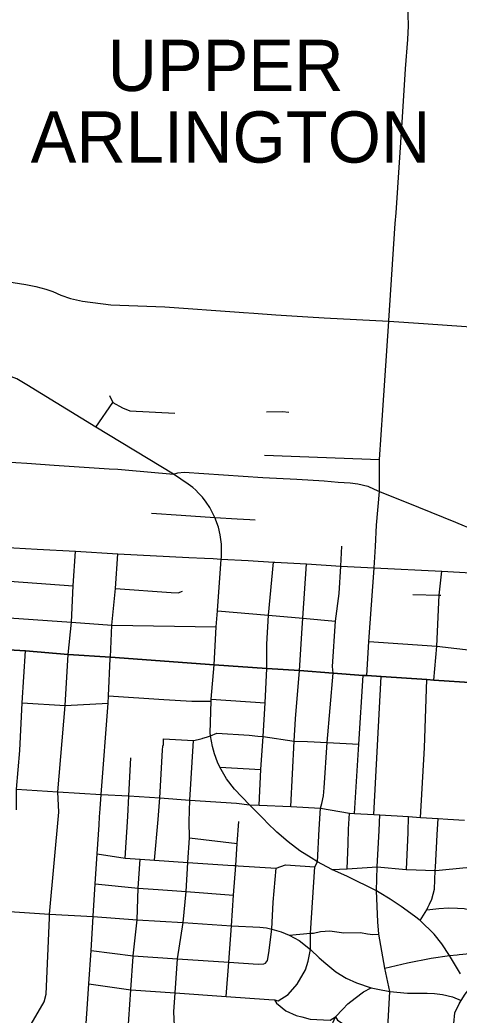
# Model space of a CAD drawing. Extents: x 1755200 to 1902939, y 644115 to 788070.
# Drawn here: x 1815056 to 1819343, y 721334 to 731049 of the extents above; entities that cross this region are included whole.
import ezdxf

# ---------------------------------------------------------------- set-up
doc = ezdxf.new("R2010")
doc.units = 0
for name, color, linetype in [('GM_X_City_Street', 7, 'Continuous'), ('GM_X_Corporation_Text', 7, 'Continuous'), ('GM_X_County_Road', 7, 'Continuous'), ('GM_X_Township', 7, 'Continuous'), ('GM_X_Township_Road', 7, 'Continuous')]:
    doc.layers.add(name, color=color, linetype=linetype)

msp = doc.modelspace()

# ---------------------------------------------------------------- linework, layer by layer
at = {"layer": 'GM_X_City_Street'}
for points in [[(1818727.1, 729165.6), (1818791.6, 730097.9), (1818818.4, 730570.5), (1818842, 730857.7), (1818848.2, 730991.2), (1818845.7, 731099.8), (1818840.7, 731192.1), (1818829.5, 731319.4), (1818772.9, 731538.4), (1818732.1, 731685.2), (1818692.3, 731806), (1818631.5, 731957.8), (1818624.1, 731979.3)], [(1818658, 728114.9), (1818720, 729062.6), (1818727.1, 729165.6)], [(1814899.1, 728496.4), (1814910.5, 728494.9), (1814989.3, 728484.1), (1815114.8, 728467.1), (1815211.4, 728446.8), (1815309.8, 728419.6), (1815379.3, 728395.9), (1815457.3, 728362), (1815548.9, 728329.8), (1815666.3, 728304.4), (1815943.7, 728268.2), (1816471, 728247.3), (1817194.8, 728196.2), (1817237.9, 728192.9)], [(1817553.2, 728170.6), (1817865.1, 728149.7), (1818026.3, 728141.3)], [(1817022.3, 725800.3), (1817024.2, 725838.5), (1817023.3, 725930.5), (1817012, 726020.8), (1816994.7, 726096.3), (1816957.6, 726190.3), (1816908.5, 726288.2), (1816875.7, 726341.1), (1816837.5, 726390.5), (1816800.2, 726430.5), (1816773.3, 726458.3), (1816743.3, 726483.3), (1816699.5, 726517.3), (1816554.6, 726613.6), (1815795.9, 727074.6), (1815124, 727487.8), (1815027.3, 727544.1), (1814923.3, 727583.5), (1814857.8, 727604.8)], [(1815930.6, 727383.2), (1815962.8, 727313), (1816057.7, 727261.8), (1816129.7, 727233.3), (1816567.8, 727210.6)], [(1815795.9, 727074.6), (1815962.8, 727313)], [(1817462.4, 727223.5), (1817618.3, 727226.9), (1817681.2, 727220.6)], [(1817442.3, 726799.8), (1818565.1, 726756.8)], [(1815124.1, 726721.8), (1815392, 726703.6)], [(1816084.6, 726655.9), (1816554.6, 726613.6)], [(1816554.6, 726613.6), (1816598.2, 726627.7), (1816658.3, 726632.4), (1817427.8, 726583.3), (1817758, 726564.7)], [(1816340.4, 726232.6), (1816628.9, 726212.9), (1816957.6, 726190.3), (1817177.9, 726178.2), (1817301.5, 726170.8), (1817351.8, 726167.5)], [(1814690.5, 725914.3), (1814701, 725913.9), (1814766.5, 725909.9), (1815223.8, 725881.8), (1815597.9, 725861.9), (1816012.9, 725835.8), (1816704.7, 725801.1), (1816857.1, 725794.4)], [(1815435.8, 723315.1), (1815428.1, 723513.4), (1815498.3, 724357.1), (1815528.3, 724855.6), (1815561, 725169.5), (1815577.1, 725525.9), (1815597.9, 725861.9)], [(1817977.6, 723150.2), (1817990.7, 723353.3), (1818003.9, 723399.2), (1818020.4, 723473.4), (1818024.8, 723551.6), (1818055.6, 723994.4), (1818114.7, 724671.6), (1818107.4, 724737.2), (1818136.5, 725180.7), (1818170.9, 725449.5), (1818190, 725717.8), (1818196.9, 725913.1)], [(1818513.5, 725698.3), (1818513.8, 725701.3), (1818525.9, 725908.5)], [(1815938.8, 724816.7), (1815939.4, 724829.2), (1815953.4, 725141.7), (1815988.6, 725498.2), (1816012.9, 725835.8)], [(1816857.1, 725794.4), (1816940.9, 725790.7), (1817021.6, 725785.5), (1817283.7, 725770.7), (1817532, 725756.8), (1817544, 725756.1)], [(1816951.7, 724754.5), (1816973, 725124.9), (1816984.3, 725281.2), (1817021.6, 725785.5), (1817022.3, 725800.3)], [(1817391.7, 723383.7), (1817409.1, 723731.8), (1817429.9, 724052.9), (1817449.8, 724382.8), (1817466.6, 724716.2), (1817466.8, 724953.4), (1817484.1, 725237.1), (1817532, 725756.8)], [(1817544, 725756.1), (1817854.9, 725737.7), (1818190, 725717.8), (1818513.8, 725701.3), (1819172.6, 725666.6), (1819572.8, 725644), (1819777.6, 725631.8), (1819956.5, 725621.7), (1820223.8, 725606.7), (1820239, 725605.8)], [(1817699, 723371.5), (1817732.8, 724009.6), (1817747.6, 724225.4), (1817784.7, 724698.3), (1817810.6, 725112.1), (1817817.1, 725208.3), (1817854.9, 725737.7)], [(1818441.7, 724647.8), (1818461.1, 724982.2), (1818513.5, 725698.3)], [(1819097.3, 724604.7), (1819124.4, 724935.9), (1819147.9, 725434.4), (1819172.6, 725666.6)], [(1814684.5, 725588.3), (1814730.6, 725585.1), (1815577.1, 725525.9)], [(1815988.6, 725498.2), (1816533.7, 725458.2), (1816601.4, 725455.6), (1816644.8, 725471.3)], [(1818890.4, 725440), (1819147.9, 725434.4), (1819163, 725434)], [(1816984.3, 725281.2), (1817484.1, 725237.1), (1817817.1, 725208.3), (1818136.5, 725180.7)], [(1814952.9, 725212.7), (1815561, 725169.5), (1815953.4, 725141.7), (1816973, 725124.9)], [(1813163.5, 725003.7), (1813252.9, 725000.2), (1813615.9, 724979.6), (1813984.1, 724943.3), (1814293.9, 724935.6), (1814336.4, 724933), (1814648, 724917.3), (1814691.9, 724915), (1814724.3, 724913.2), (1815112.2, 724889.3), (1815528.3, 724855.6), (1815939.4, 724829.2), (1816951.7, 724754.5), (1817466.6, 724716.2), (1817784.7, 724698.3), (1818114.7, 724671.6), (1818406, 724647.8), (1818441.7, 724647.8), (1818582.9, 724639.3), (1819027.7, 724609.4), (1819097.3, 724604.7), (1819495.6, 724577.5)], [(1815023.8, 723337.6), (1815022.3, 723538.9), (1815055.7, 723915.5), (1815078.7, 724381.5), (1815112.2, 724889.3)], [(1818461.1, 724982.2), (1819124.4, 724935.9), (1819515.5, 724888.8)], [(1815839, 723347.9), (1815848.3, 723488), (1815917.2, 724377.7), (1815921.1, 724452), (1815938.8, 724816.7)], [(1817439.6, 723242.4), (1817296.2, 723388), (1817150.4, 723538.2), (1817072.3, 723641.5), (1817007.2, 723755.2), (1816985.4, 723803.8), (1816956.8, 723883.7), (1816936.8, 723957.4), (1816917.4, 724060.7), (1816914, 724090.2), (1816923.5, 724398.4), (1816924.4, 724418.3), (1816951.7, 724754.5)], [(1818322.8, 723301.9), (1818364, 723979), (1818406, 724647.8)], [(1818510.9, 723291.4), (1818582.9, 724639.3)], [(1818965, 723264.3), (1819005.3, 723942.5), (1819027.7, 724609.4)], [(1815921.1, 724452), (1816461.7, 724415.7), (1816734.3, 724398.4), (1816923.5, 724398.4)], [(1816924.4, 724418.3), (1817449.8, 724382.8)], [(1815078.7, 724381.5), (1815498.3, 724357.1), (1815917.2, 724377.7)], [(1816458.3, 723977), (1816456.8, 724030.4), (1816750.2, 724015.6), (1816794.5, 724025.2), (1816836.1, 724034.7), (1816840.2, 724035.9)], [(1816707.7, 723223.9), (1816716.3, 723432.3), (1816750.2, 724015.6)], [(1816840.2, 724035.9), (1816878.7, 724046.8), (1816917.4, 724060.7), (1816977.6, 724085.9), (1817295.3, 724065.9), (1817379.4, 724057.8)], [(1817379.4, 724057.8), (1817429.9, 724052.9), (1817732.8, 724009.6), (1817862.8, 724004.1), (1818055.6, 723994.4), (1818364, 723979)], [(1816407, 723244.5), (1816421.3, 723454.6), (1816447, 723920.7), (1816450.5, 723960.9), (1816458.3, 723977)], [(1816108.4, 723272.2), (1816120.5, 723473.7), (1816139.1, 723846.6)], [(1817007.2, 723755.2), (1817409.1, 723731.8)], [(1815022.3, 723538.9), (1815428.1, 723513.4), (1815848.3, 723488), (1816120.5, 723473.7), (1816421.3, 723454.6), (1816716.3, 723432.3), (1817171.2, 723404.5), (1817296.2, 723388), (1817391.7, 723383.7), (1817699, 723371.5), (1817990.7, 723353.3), (1818272.2, 723304.5), (1818322.8, 723301.9), (1818510.9, 723291.4), (1818569.4, 723288.1), (1818850.3, 723271.2), (1818965, 723264.3), (1819139.5, 723253.8), (1819233, 723248.1), (1819394.6, 723236.7)], [(1815828.6, 723190.5), (1815833.8, 723269.8), (1815839, 723347.9)], [(1815344, 722283.3), (1815345.5, 722319.7), (1815435.8, 723315.1)], [(1816083.9, 722867.3), (1816108.4, 723272.2)], [(1816368.8, 722847.8), (1816407, 723244.5)], [(1819357.8, 721736.1), (1819249.3, 721914.9), (1819173.8, 722029.5), (1819100, 722123.3), (1818962.9, 722258.7), (1818907.3, 722301.2), (1818777.1, 722394.9), (1818668.6, 722466.1), (1818561, 722531.2), (1818534.9, 722547.7), (1818253.7, 722686.6), (1818099.2, 722756.9), (1817960.3, 722831.6), (1817898.6, 722868), (1817788.4, 722939.2), (1817675.5, 723024.3), (1817564.9, 723118.9), (1817469.8, 723211.8), (1817439.6, 723242.4)], [(1818263.2, 723148.5), (1818272.2, 723304.5)], [(1818561.9, 723136.2), (1818569.4, 723288.1)], [(1818847, 723117.6), (1818850.3, 723271.2)], [(1819128, 723095), (1819139.5, 723253.8)], [(1815772.6, 722298.4), (1815791.2, 722616.4), (1815809.7, 722907.7), (1815828.6, 723190.5)], [(1816584, 721201), (1816563.6, 721228.8), (1816557.8, 721365.2), (1816571.2, 721550), (1816588.5, 721789.1), (1816595.4, 721883.5), (1816649.6, 722238.5), (1816677.9, 722539.8), (1816696.8, 722825.4), (1816712.5, 723063.3), (1816707.7, 723223.9)], [(1817069.3, 721515.7), (1817094, 721850.2), (1817122.9, 722206), (1817142.2, 722506.4), (1817163.2, 722793.9), (1817178, 723010), (1817192.5, 723222.5)], [(1817540.7, 721481.8), (1817576.9, 721474.2), (1817674.4, 721535.6), (1817763.3, 721635.1), (1817843.4, 721775.6), (1817871.2, 721859.1), (1817893.3, 721974), (1817892.1, 722135.3), (1817935.1, 722782.1), (1817960.3, 722831.6), (1817977.6, 723150.2)], [(1818251.1, 722763), (1818259, 723006), (1818263.2, 723148.5)], [(1816712.5, 723063.3), (1817178, 723010)], [(1818559.3, 719644.4), (1818600.5, 720334.6), (1818647.9, 721210.2), (1818666, 721565.1), (1818619.1, 721790.8), (1818559.2, 722124.1), (1818550.5, 722244.8), (1818534.9, 722547.7), (1818544.5, 722781.2), (1818561.9, 723136.2)], [(1818829.8, 722756), (1818847, 723117.6)], [(1818962.9, 722258.7), (1819028, 722361.1), (1819038.4, 722383.7), (1819054, 722418.4), (1819075.7, 722466.1), (1819101.8, 722565.1), (1819108.7, 722745.9), (1819112, 722777.8), (1819128, 723095)], [(1815809.7, 722907.7), (1816083.9, 722867.3), (1816230.1, 722857.3), (1816368.8, 722847.8), (1816696.8, 722825.4), (1817086.8, 722798.7), (1817143.7, 722795.1), (1817163.2, 722793.9), (1817184.9, 722792.5)], [(1816109.5, 721151), (1816139.4, 721581.5), (1816162, 721906.2), (1816162.4, 721912.2), (1816201.7, 722264), (1816209.6, 722573.2), (1816230.1, 722857.3)], [(1817184.9, 722792.5), (1817556.4, 722768.8), (1817646.9, 722800.3), (1817935.1, 722782.1)], [(1817451.9, 721841.9), (1817473.6, 721868.3), (1817484.7, 721942.7), (1817515.1, 722173.5), (1817528.5, 722436.9), (1817556.4, 722768.8)], [(1818099.2, 722756.9), (1818251.1, 722763), (1818544.5, 722781.2), (1818825.6, 722756.1), (1818829.8, 722756), (1819108.7, 722745.9), (1819114.4, 722745.7), (1819413.2, 722776.1), (1819702.8, 722758.8), (1819883.9, 722748)], [(1815791.2, 722616.4), (1816209.6, 722573.2), (1816404.2, 722559.4), (1816677.9, 722539.8), (1817142.2, 722506.4)], [(1819028, 722361.1), (1819146, 722373.3), (1819238, 722381.1), (1819327.5, 722377.6), (1819392.6, 722373.3), (1819435.1, 722364.6), (1819635, 722320.7), (1819798.7, 722311.4)], [(1814953.4, 722345.2), (1815345.5, 722319.7), (1815772.6, 722297.8), (1816201.7, 722264), (1816649.6, 722238.5), (1817122.9, 722206), (1817399.1, 722192.1), (1817461.7, 722185.1), (1817515.1, 722173.5), (1817605.6, 722145.7), (1817684.5, 722113.2), (1817781.9, 722062.2), (1817893.3, 721974), (1817976.8, 721892.8), (1818041.2, 721837.1), (1818139.2, 721755.9), (1818241.3, 721695.5), (1818341.1, 721647.7), (1818485.4, 721601.7), (1818550.8, 721586.6), (1818666, 721565.1), (1818837.9, 721546.9), (1818920.3, 721547.7), (1819030.6, 721546.9), (1819101.8, 721544.3), (1819180.7, 721535.6), (1819278.8, 721511.3), (1819363.6, 721476.5)], [(1815152.1, 720480.4), (1815090.7, 720998), (1815080.9, 721074), (1815119, 721161.3), (1815167.7, 721246.4), (1815292.5, 721464.5), (1815312.9, 721537.2), (1815344, 722283.3)], [(1815650.7, 720462.1), (1815662.1, 720643.2), (1815673.4, 720841.8), (1815689, 721057.9), (1815728.6, 721639), (1815751.1, 721965.5), (1815772.6, 722297.8), (1815772.6, 722298.4)], [(1817684.5, 722113.2), (1817892.1, 722135.3), (1817921.3, 722134.8), (1817989.2, 722151.7), (1818081.4, 722156.8), (1818218, 722136.4), (1818379.5, 722140.6), (1818447.2, 722128.4), (1818500.2, 722121.5), (1818559.2, 722124.1)], [(1815751.1, 721965.5), (1816162.4, 721912.2), (1816595.4, 721883.5), (1817094, 721850.2), (1817381.9, 721831), (1817436, 721833.7), (1817451.9, 721841.9)], [(1818619.1, 721790.8), (1818839.6, 721843.7), (1819068.8, 721888.9), (1819249.3, 721914.9), (1819322.7, 721923.8)], [(1819322.7, 721923.8), (1819343.1, 721926.2), (1819449, 721935.8), (1819564.4, 721944.4), (1819660.8, 721946.2), (1819707.5, 721943.2)], [(1815728.6, 721639), (1816139.4, 721581.5), (1816571.2, 721550), (1817069.3, 721515.7), (1817484.5, 721487.1), (1817540.7, 721481.8), (1817561.2, 721449.9), (1817650.3, 721376.8), (1817753.2, 721329.9), (1817808.6, 721315.7), (1817887.9, 721295.4), (1818084.6, 721283.9), (1818136.1, 721315.9), (1818154.7, 721284.7), (1818406.6, 721123.2), (1818447.5, 721174.6), (1818496.3, 721203.6), (1818543.7, 721212.9), (1818647.9, 721210.2), (1818967, 721193.1), (1819174, 721174.6), (1819234.7, 721154.9), (1819283.3, 721129.9)], [(1817929.9, 719682.6), (1817956.2, 720340.7), (1817979, 720913.3), (1818038.9, 721094.6), (1818136.1, 721315.9), (1818206.5, 721392.6), (1818256.6, 721444.2), (1818328.6, 721499), (1818410, 721560), (1818485.4, 721601.7)], [(1819187.7, 719608), (1819221.5, 720265), (1819283.3, 721129.9), (1819291.9, 721250.7), (1819302.5, 721357.2), (1819343.9, 721443.6), (1819363.6, 721476.5), (1819400.4, 721538.2), (1819441.2, 721588.5)]]:
    msp.add_lwpolyline(points, dxfattribs=at)
at = {"layer": 'GM_X_County_Road'}
for points in [[(1817237.9, 728192.9), (1817338.2, 728185), (1817553.2, 728170.6)], [(1818026.3, 728141.3), (1818657.6, 728108.4)], [(1818525.9, 725908.5), (1818538.1, 726116.2), (1818565.7, 726445.5), (1818565.1, 726756.8), (1818598.4, 727237.6), (1818657.6, 728108.4), (1818658, 728114.9)], [(1818657.6, 728108.4), (1818994.6, 728084.4), (1819597.7, 728043.4), (1820129.2, 728008.9)], [(1817758, 726564.7), (1818027.1, 726549.6), (1818161.6, 726536.3), (1818277.9, 726529.8), (1818354.2, 726521.1), (1818451.6, 726497.8), (1818513.2, 726469.6), (1818565.7, 726445.5), (1818945.1, 726290.7), (1819306.3, 726145.3), (1819393.1, 726109.8), (1819490.3, 726070.2), (1819555.4, 726051.1), (1819638.7, 726041.6), (1819811.5, 726029.4), (1820245.3, 726003), (1820409.4, 725993.2)]]:
    msp.add_lwpolyline(points, dxfattribs=at)
at = {"layer": 'GM_X_Township'}
msp.add_lwpolyline([(1819495.6, 724577.5), (1819097.4, 724604.6), (1819027.7, 724609.4), (1818582.9, 724639.3), (1818441.7, 724647.8), (1818406.1, 724647.8), (1818114.7, 724671.6), (1817784.7, 724698.3), (1817466.6, 724716.2), (1816951.7, 724754.4), (1815939.4, 724829.2), (1815528.3, 724855.6), (1815112.3, 724889.3), (1814724.3, 724913.2), (1814691.9, 724915)], dxfattribs=at)
at = {"layer": 'GM_X_Township_Road'}
for points in [[(1814909.8, 726736.4), (1815124.1, 726721.8)], [(1815392, 726703.6), (1815927.7, 726667.1), (1816011.6, 726662.4), (1816084.6, 726655.9)]]:
    msp.add_lwpolyline(points, dxfattribs=at)

# ---------------------------------------------------------------- texts
at = {"layer": 'GM_X_Corporation_Text'}
for s, p in [('UPPER', (1815912, 730354.3)), ('ARLINGTON', (1815161.8, 729655.5))]:
    msp.add_text(s, height=500, rotation=0.00001, dxfattribs=at).set_placement(p)

doc.saveas('drawing.dxf')
